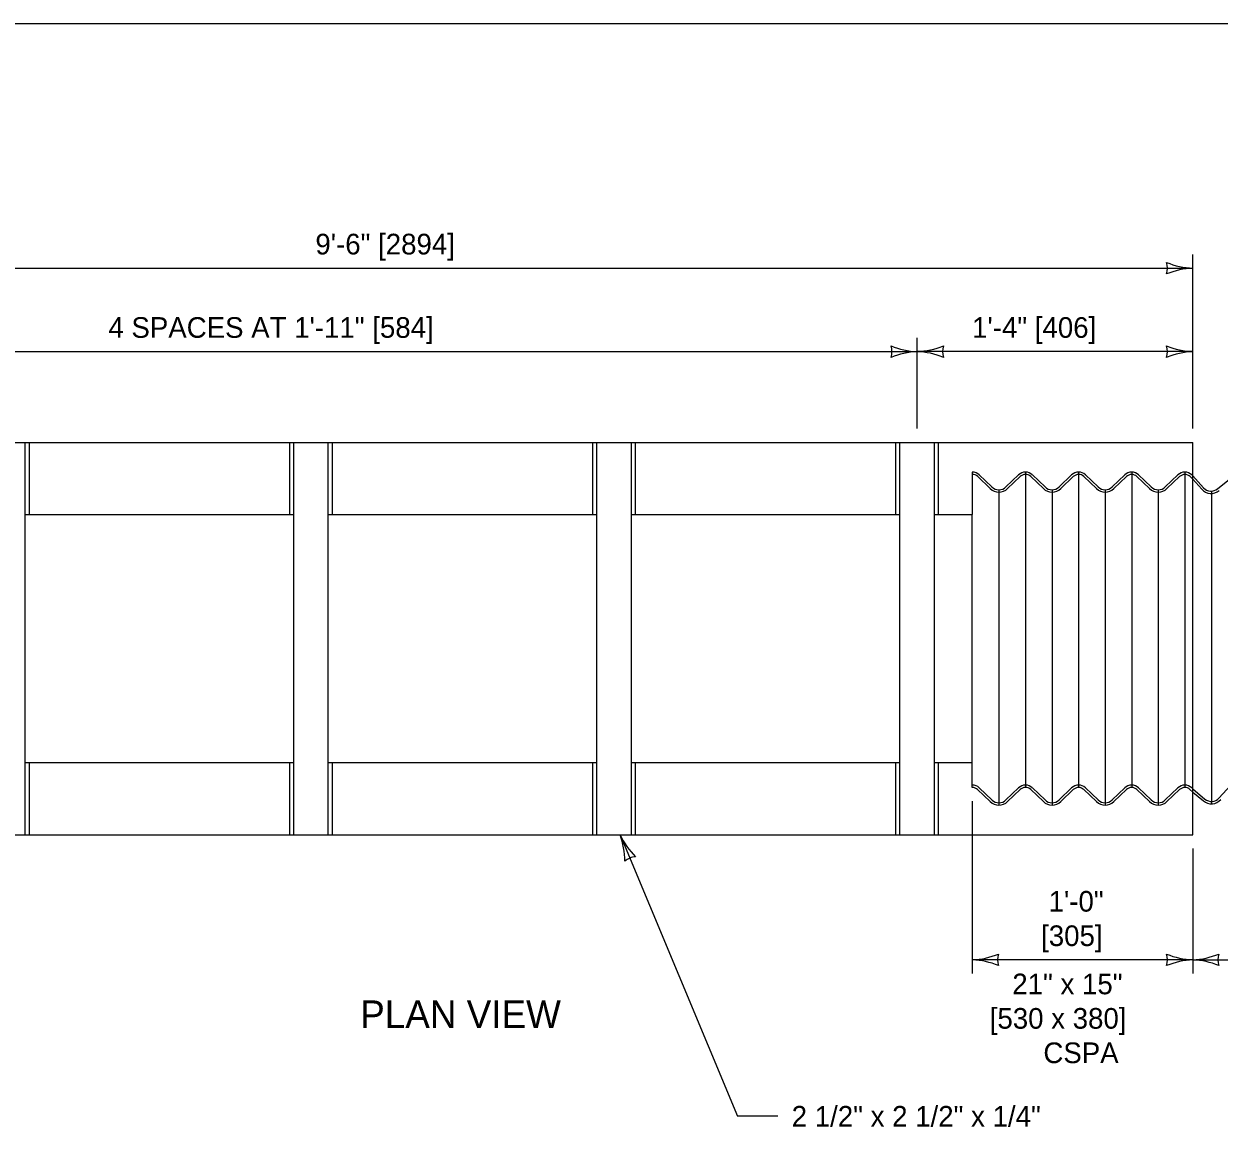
# Model space of a CAD drawing. Extents: x 49991.4 to 50021, y 49987.6 to 50011.4.
# Drawn here: x 50003.173 to 50006.644, y 50008.041 to 50011.263 of the extents above; entities that cross this region are included whole.
import ezdxf

# ---------------------------------------------------------------- set-up
doc = ezdxf.new("R2010")
doc.units = 0
for name, color, linetype in [('Level 1', 7, 'Continuous'), ('Level 2', 7, 'Continuous'), ('Level 3', 7, 'Continuous'), ('Level 4', 7, 'Continuous')]:
    doc.layers.add(name, color=color, linetype=linetype)

msp = doc.modelspace()

# ---------------------------------------------------------------- linework, layer by layer
at = {"layer": 'Level 1'}
for p, q in [((50002.0071, 50010.0473), (50006.5671, 50010.0473)), ((50003.1771, 50008.9073), (50003.1771, 50010.0473)), ((50003.1891, 50009.8374), (50003.1891, 50010.0473)), ((50003.9451, 50009.8374), (50003.9451, 50010.0473)), ((50003.9571, 50008.9073), (50003.9571, 50010.0473)), ((50004.0571, 50008.9073), (50004.0571, 50010.0473)), ((50004.0691, 50009.8374), (50004.0691, 50010.0473)), ((50004.8251, 50009.8374), (50004.8251, 50010.0473)), ((50004.8371, 50008.9073), (50004.8371, 50010.0473)), ((50004.9371, 50008.9073), (50004.9371, 50010.0473)), ((50004.9491, 50009.8374), (50004.9491, 50010.0473)), ((50005.7051, 50009.8374), (50005.7051, 50010.0473)), ((50005.7171, 50008.9073), (50005.7171, 50010.0473)), ((50005.8171, 50008.9073), (50005.8171, 50010.0473)), ((50005.8291, 50009.8374), (50005.8291, 50010.0473)), ((50006.5671, 50008.9073), (50006.5671, 50010.0473)), ((50006.5671, 50009.9504), (50006.5987, 50009.9156)), ((50006.5671, 50009.9408), (50006.5935, 50009.911)), ((50006.6392, 50009.9126), (50006.6783, 50009.9448)), ((50006.5935, 50009.911), (50006.5935, 50009.911)), ((50006.5987, 50009.9156), (50006.5987, 50009.9156)), ((50006.6214, 50009.9057), (50006.6214, 50008.9975)), ((50003.1771, 50009.8374), (50003.9571, 50009.8374)), ((50004.0571, 50009.8374), (50004.8371, 50009.8374)), ((50004.9371, 50009.8374), (50005.7171, 50009.8374)), ((50005.8171, 50009.8374), (50005.9271, 50009.8374)), ((50005.9271, 50009.1174), (50005.9271, 50009.8374)), ((50003.1771, 50009.1174), (50003.9571, 50009.1174)), ((50003.1891, 50008.9073), (50003.1891, 50009.1174)), ((50003.9451, 50008.9073), (50003.9451, 50009.1174)), ((50004.0571, 50009.1174), (50004.8371, 50009.1174)), ((50004.0691, 50008.9073), (50004.0691, 50009.1174)), ((50004.8251, 50008.9073), (50004.8251, 50009.1174)), ((50004.9371, 50009.1174), (50005.7171, 50009.1174)), ((50004.9491, 50008.9073), (50004.9491, 50009.1174)), ((50005.7051, 50008.9073), (50005.7051, 50009.1174)), ((50005.8171, 50009.1174), (50005.9271, 50009.1174)), ((50005.8291, 50008.9073), (50005.8291, 50009.1174)), ((50006.5671, 50009.0412), (50006.6027, 50009.0113)), ((50006.5671, 50009.0316), (50006.5982, 50009.0061)), ((50006.6432, 50009.0143), (50006.6775, 50009.0519)), ((50006.5982, 50009.0061), (50006.5982, 50009.0061)), ((50006.6027, 50009.0113), (50006.6027, 50009.0113)), ((50006.6432, 50009.0143), (50006.6432, 50009.0143)), ((50002.0071, 50008.9073), (50006.5671, 50008.9073))]:
    msp.add_line(p, q, dxfattribs=at)
msp.add_lwpolyline([(50008.6146, 50011.2628), (50000.3356, 50011.2628), (50000.3356, 50000.0624), (50008.6146, 50000.0624)], close=True, dxfattribs=at)
for centre, radius, start, end in [((50006.6204, 50009.9347), 0.0358, 221.2467, 265.8403), ((50006.6204, 50009.9347), 0.0289, 221.2467, 265.8403), ((50006.6204, 50009.9347), 0.0358, 265.8403, 310.4339), ((50006.6204, 50009.9347), 0.0289, 265.8403, 310.4339), ((50006.6215, 50009.0333), 0.0358, 229.5456, 274.1392), ((50006.6215, 50009.0333), 0.0289, 229.5456, 274.1392), ((50006.6215, 50009.0333), 0.0289, 274.1392, 318.7329), ((50006.6215, 50009.0333), 0.0358, 274.1392, 318.7329)]:
    msp.add_arc(centre, radius, start, end, dxfattribs=at)
at = {"layer": 'Level 3'}
for p, q in [((50006.5671, 50010.0873), (50006.5671, 50010.5932)), ((50002.0071, 50010.5532), (50006.5671, 50010.5532)), ((50005.7671, 50010.0873), (50005.7671, 50010.351)), ((50002.2471, 50010.311), (50005.7671, 50010.311)), ((50006.5671, 50010.311), (50005.7671, 50010.311)), ((50005.9271, 50009.005), (50005.9271, 50008.5043)), ((50004.9043, 50008.9073), (50005.2457, 50008.0899)), ((50006.5671, 50008.8673), (50006.5671, 50008.5043)), ((50006.5671, 50008.5443), (50005.9271, 50008.5443)), ((50006.5671, 50008.5443), (50007.4699, 50008.5443)), ((50005.3627, 50008.0899), (50005.2457, 50008.0899))]:
    msp.add_line(p, q, dxfattribs=at)
for centre, radius, start, end in [((50006.5763, 50010.7753), 0.2223, 247.456, 267.6395), ((50006.4389, 50010.5532), 0.0548, 342.1388, 17.8612), ((50006.5786, 50010.3205), 0.233, 92.8273, 112.0772), ((50005.7763, 50010.5331), 0.2223, 247.456, 267.6395), ((50005.6389, 50010.311), 0.0548, 342.1388, 17.8612), ((50005.7786, 50010.0783), 0.233, 92.8273, 112.0772), ((50005.7556, 50010.5437), 0.233, 272.8273, 292.0772), ((50005.7579, 50010.0889), 0.2223, 67.456, 87.6395), ((50005.8953, 50010.311), 0.0548, 162.1388, 197.8612), ((50006.5763, 50010.5331), 0.2223, 247.456, 267.6395), ((50006.4389, 50010.311), 0.0548, 342.1388, 17.8612), ((50006.5786, 50010.0783), 0.233, 92.8273, 112.0772), ((50004.696, 50008.8297), 0.2223, 0.2515, 20.435), ((50005.1144, 50009.0081), 0.233, 205.6228, 224.8727), ((50004.954, 50008.7891), 0.0548, 94.9343, 130.6567), ((50005.9156, 50008.777), 0.233, 272.8273, 292.0772), ((50005.9179, 50008.3222), 0.2223, 67.456, 87.6395), ((50006.0553, 50008.5443), 0.0548, 162.1388, 197.8612), ((50006.5763, 50008.7664), 0.2223, 247.456, 267.6395), ((50006.4389, 50008.5443), 0.0548, 342.1388, 17.8612), ((50006.5786, 50008.3116), 0.233, 92.8273, 112.0772), ((50006.5556, 50008.777), 0.233, 272.8273, 292.0772), ((50006.5579, 50008.3222), 0.2223, 67.456, 87.6395), ((50006.6953, 50008.5443), 0.0548, 162.1388, 197.8612)]:
    msp.add_arc(centre, radius, start, end, dxfattribs=at)
at = {"layer": 'Level 4'}
for p, q in [((50005.9271, 50009.9611), (50005.9271, 50009.8374)), ((50006.0814, 50009.9611), (50006.0814, 50009.045)), ((50006.2358, 50009.9611), (50006.2358, 50009.045)), ((50006.39, 50009.9611), (50006.39, 50009.045)), ((50006.5443, 50009.9611), (50006.5443, 50009.045)), ((50005.9427, 50009.9479), (50005.9791, 50009.913)), ((50005.9472, 50009.9528), (50005.984, 50009.918)), ((50006.0246, 50009.918), (50006.0612, 50009.9528)), ((50006.0295, 50009.913), (50006.0661, 50009.9479)), ((50006.1334, 50009.913), (50006.0966, 50009.948)), ((50006.1383, 50009.918), (50006.1014, 50009.953)), ((50006.2155, 50009.9528), (50006.1789, 50009.918)), ((50006.2204, 50009.9479), (50006.1837, 50009.913)), ((50006.2507, 50009.9482), (50006.2877, 50009.913)), ((50006.2557, 50009.9531), (50006.2926, 50009.918)), ((50006.3332, 50009.918), (50006.3698, 50009.9528)), ((50006.338, 50009.913), (50006.3746, 50009.9479)), ((50006.442, 50009.913), (50006.4051, 50009.9481)), ((50006.4468, 50009.918), (50006.41, 50009.953)), ((50006.5241, 50009.9528), (50006.4875, 50009.918)), ((50006.5289, 50009.9479), (50006.4923, 50009.913)), ((50006.5597, 50009.9479), (50006.5671, 50009.9408)), ((50006.5645, 50009.9528), (50006.5671, 50009.9504)), ((50006.0043, 50009.9096), (50006.0043, 50008.9936)), ((50006.1586, 50009.9096), (50006.1586, 50008.9936)), ((50006.3129, 50009.9096), (50006.3129, 50008.9936)), ((50006.4671, 50009.9096), (50006.4671, 50008.9936)), ((50005.9271, 50009.045), (50005.9271, 50009.1174)), ((50005.9425, 50009.0387), (50005.9791, 50009.0039)), ((50005.9474, 50009.0438), (50005.9848, 50009.0084)), ((50006.0246, 50009.0088), (50006.0612, 50009.0437)), ((50006.0295, 50009.0039), (50006.0661, 50009.0387)), ((50006.1334, 50009.0039), (50006.0966, 50009.0389)), ((50006.1383, 50009.0088), (50006.1014, 50009.0438)), ((50006.2155, 50009.0437), (50006.1789, 50009.0088)), ((50006.2204, 50009.0387), (50006.1837, 50009.0039)), ((50006.2508, 50009.0389), (50006.2877, 50009.0039)), ((50006.2557, 50009.0439), (50006.2926, 50009.0088)), ((50006.3332, 50009.0088), (50006.3698, 50009.0437)), ((50006.338, 50009.0039), (50006.3746, 50009.0387)), ((50006.442, 50009.0039), (50006.4051, 50009.0389)), ((50006.4468, 50009.0088), (50006.41, 50009.0438)), ((50006.5241, 50009.0437), (50006.4875, 50009.0088)), ((50006.5289, 50009.0387), (50006.4923, 50009.0039)), ((50006.559, 50009.0392), (50006.5671, 50009.0316)), ((50006.5645, 50009.0437), (50006.5671, 50009.0412))]:
    msp.add_line(p, q, dxfattribs=at)
for centre, radius, start, end in [((50006.0814, 50009.9321), 0.0289, 90, 134.2931), ((50006.2357, 50009.9321), 0.0289, 90, 134.2931), ((50006.39, 50009.9321), 0.0289, 90, 134.2931), ((50006.5443, 50009.9321), 0.0289, 90, 134.2931), ((50006.5443, 50009.9321), 0.0289, 45.7069, 90), ((50006.0814, 50009.9321), 0.022, 90, 134.2931), ((50006.2357, 50009.9321), 0.022, 90, 134.2931), ((50006.39, 50009.9321), 0.022, 90, 134.2931), ((50006.5443, 50009.9321), 0.022, 90, 134.2931), ((50006.5443, 50009.9321), 0.022, 45.7069, 90), ((50006.0043, 50009.9386), 0.0358, 225.4064, 270), ((50006.0043, 50009.9386), 0.0289, 225.4064, 270), ((50006.0043, 50009.9386), 0.0289, 270, 314.5936), ((50006.0043, 50009.9386), 0.0358, 270, 314.5936), ((50006.1586, 50009.9386), 0.0358, 225.4064, 270), ((50006.1586, 50009.9386), 0.0289, 225.4064, 270), ((50006.1586, 50009.9386), 0.0289, 270, 314.5936), ((50006.1586, 50009.9386), 0.0358, 270, 314.5936), ((50006.3129, 50009.9386), 0.0358, 225.4064, 270), ((50006.3129, 50009.9386), 0.0289, 225.4064, 270), ((50006.3129, 50009.9386), 0.0289, 270, 314.5936), ((50006.3129, 50009.9386), 0.0358, 270, 314.5936), ((50006.4672, 50009.9386), 0.0358, 225.4064, 270), ((50006.4672, 50009.9386), 0.0289, 225.4064, 270), ((50006.4672, 50009.9386), 0.0289, 270, 314.5936), ((50006.4672, 50009.9386), 0.0358, 270, 314.5936), ((50006.0814, 50009.023), 0.0289, 90, 134.2931), ((50006.0814, 50009.023), 0.022, 90, 134.2931), ((50006.2357, 50009.023), 0.0289, 90, 134.2931), ((50006.2357, 50009.023), 0.022, 90, 134.2931), ((50006.39, 50009.023), 0.0289, 90, 134.2931), ((50006.39, 50009.023), 0.022, 90, 134.2931), ((50006.5443, 50009.023), 0.0289, 90, 134.2931), ((50006.5443, 50009.023), 0.022, 90, 134.2931), ((50006.5443, 50009.023), 0.0289, 45.7069, 90), ((50006.0043, 50009.0294), 0.0358, 225.4064, 270), ((50006.0043, 50009.0294), 0.0289, 270, 314.5936), ((50006.0043, 50009.0294), 0.0358, 270, 314.5936), ((50006.1586, 50009.0294), 0.0358, 225.4064, 270), ((50006.1586, 50009.0294), 0.0289, 225.4064, 270), ((50006.1586, 50009.0294), 0.0289, 270, 314.5936), ((50006.1586, 50009.0294), 0.0358, 270, 314.5936), ((50006.3129, 50009.0294), 0.0358, 225.4064, 270), ((50006.3129, 50009.0294), 0.0289, 225.4064, 270), ((50006.3129, 50009.0294), 0.0289, 270, 314.5936), ((50006.3129, 50009.0294), 0.0358, 270, 314.5936), ((50006.4672, 50009.0294), 0.0358, 225.4064, 270), ((50006.4672, 50009.0294), 0.0289, 225.4064, 270), ((50006.4672, 50009.0294), 0.0289, 270, 314.5936), ((50006.4672, 50009.0294), 0.0358, 270, 314.5936)]:
    msp.add_arc(centre, radius, start, end, dxfattribs=at)
for centre, major_axis, ratio, start_param, end_param in [((50005.9271, 50009.9321), (0, 0.029), 0.99255, 5.510125, 6.283185), ((50006.0814, 50009.9326), (0.0286, 0), 0.994455, 0.797736, 1.570796), ((50006.2357, 50009.9325), (0, 0.0287), 0.992869, 5.510125, 6.283185), ((50006.39, 50009.9326), (0.0286, 0), 0.994059, 0.797736, 1.570796), ((50005.9271, 50009.9321), (0.0223, 0), 0.991901, 0.797736, 1.570796), ((50006.0814, 50009.9327), (0.0217, 0), 0.989773, 0.797736, 1.570796), ((50006.2357, 50009.9327), (0, 0.0216), 0.991332, 5.510125, 6.283185), ((50006.39, 50009.9327), (0.0216, 0), 0.991073, 0.797736, 1.570796), ((50005.9271, 50009.0229), (0, 0.0292), 0.995268, 5.510125, 6.283185), ((50005.9271, 50009.0229), (0, 0.0221), 0.998883, 5.510125, 6.283185), ((50006.0814, 50009.0234), (0.0286, 0), 0.99636, 0.797736, 1.570796), ((50006.0814, 50009.0234), (0.0217, 0), 0.996887, 0.797736, 1.570796), ((50006.2357, 50009.0233), (0, 0.0287), 0.994763, 5.510125, 6.283185), ((50006.2357, 50009.0234), (0, 0.0216), 0.998487, 5.510125, 6.283185), ((50006.39, 50009.0234), (0.0286, 0), 0.995961, 0.797736, 1.570796), ((50006.39, 50009.0234), (0.0216, 0), 0.999131, 0.797736, 1.570796), ((50006.5443, 50009.0239), (0, 0.0213), 0.988705, 5.510125, 6.283185), ((50006.0043, 50009.0281), (0.0277, 0), 0.995867, 3.934083, 4.712389)]:
    msp.add_ellipse(centre, major_axis=major_axis, ratio=ratio, start_param=start_param, end_param=end_param, dxfattribs=at)

# ---------------------------------------------------------------- texts
at = {"layer": 'Level 2'}
for s, height, p in [('9\'-6" [2894]', 0.06, (50004.0196, 50010.5932)), ('4 SPACES AT 1\'-11" [584]', 0.06, (50003.4185, 50010.351)), ('1\'-4" [406]', 0.06, (50005.9265, 50010.351)), ('1\'-0"', 0.06, (50006.1487, 50008.6843)), ('[305]', 0.06, (50006.1269, 50008.5843)), ('21" x 15"', 0.06, (50006.0432, 50008.4443)), ('PLAN VIEW', 0.08, (50004.1498, 50008.3464)), ('[530 x 380]', 0.06, (50005.9777, 50008.3443)), ('CSPA', 0.06, (50006.1335, 50008.2443)), ('2 1/2" x 2 1/2" x 1/4" ', 0.06, (50005.4027, 50008.0599))]:
    msp.add_text(s, height=height, dxfattribs=at).set_placement(p)

doc.saveas('drawing.dxf')
